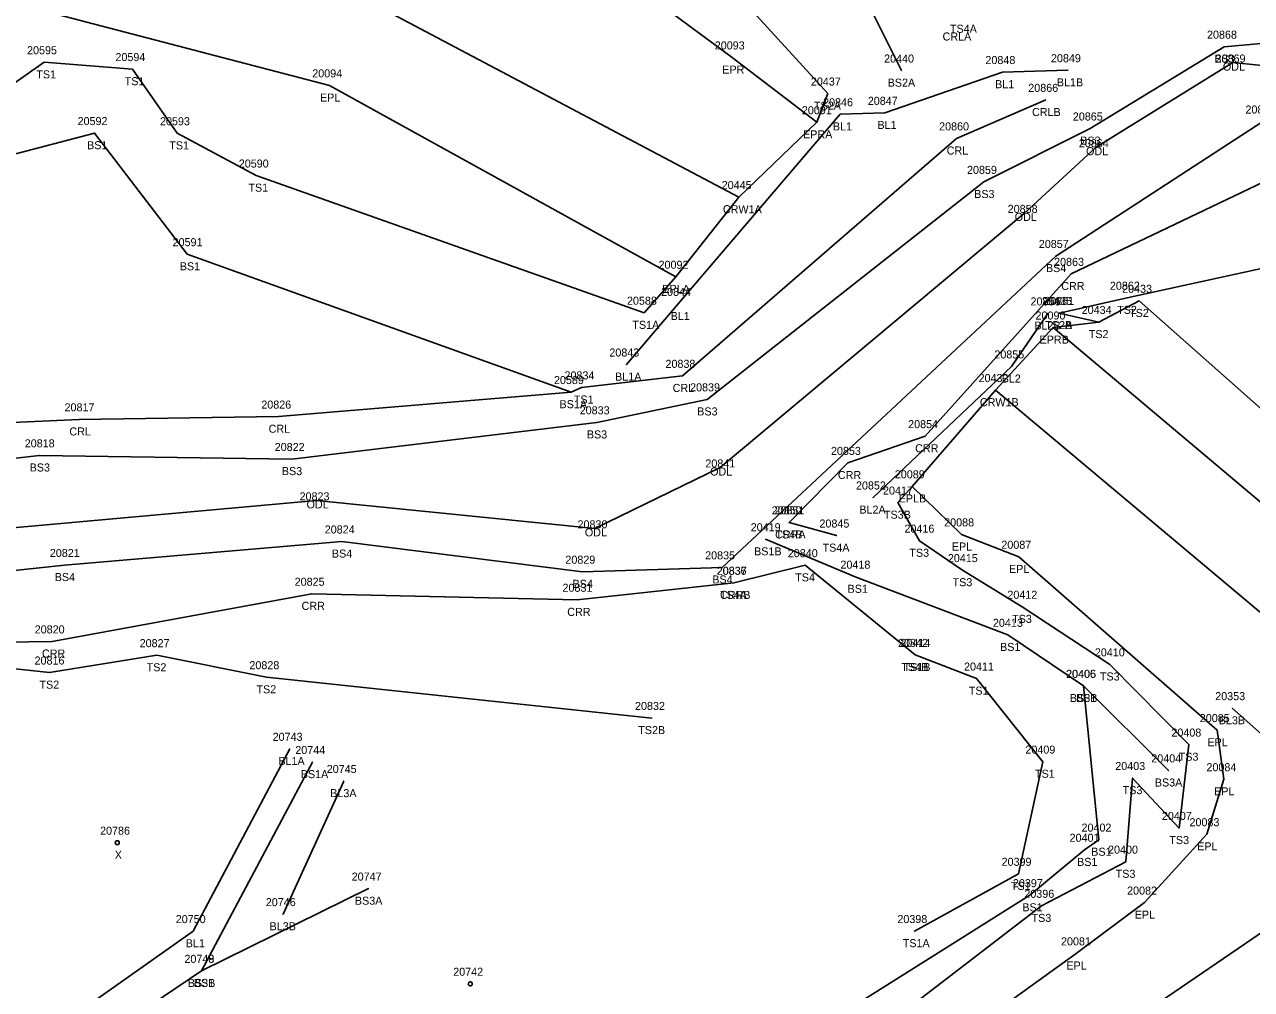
# Model space of a CAD drawing. Extents: x 1813127 to 1818290, y 1178171 to 1179900.
# Drawn here: x 1813651.9 to 1813804.5, y 1178619.3 to 1178739.3 of the extents above; entities that cross this region are included whole.
import ezdxf

# ---------------------------------------------------------------- set-up
doc = ezdxf.new("R2010")
doc.units = 0
for name, color, linetype in [('RD_DTM_BkLn1', 7, 'Continuous'), ('RD_DTM_BkLn2', 7, 'Continuous'), ('RD_EX_H2O', 7, 'Continuous'), ('RD_EX_H2O_txCode', 7, 'Continuous'), ('RD_EX_Road', 7, 'Continuous'), ('RD_EX_Road_txCode', 7, 'Continuous'), ('RD_SMD_Locator', 7, 'Continuous'), ('RD_SMD_Misc', 7, 'Continuous')]:
    doc.layers.add(name, color=color, linetype=linetype)

msp = doc.modelspace()

# ---------------------------------------------------------------- linework, layer by layer
at = {"layer": 'RD_DTM_BkLn1'}
for p, q in [((1813820.26, 1178638.1), (1813802.14, 1178654.3)), ((1813691.64, 1178645.24), (1813684.08, 1178628.68))]:
    msp.add_line(p, q, dxfattribs=at)
for points in [[(1813740.76, 1178717.86), (1813693.97, 1178742.65), (1813652.18, 1178753.85), (1813643.74, 1178755.64), (1813595, 1178763.51), (1813546.44, 1178770.61), (1813497.6, 1178777.62), (1813448.59, 1178785.89), (1813401.09, 1178795.04), (1813353.48, 1178806.76), (1813306.05, 1178819.85), (1813260.03, 1178834.12), (1813213.64, 1178849.47), (1813166.61, 1178866.29)], [(1813726.79, 1178697.04), (1813733.22, 1178704.58), (1813753.39, 1178728.16), (1813758.93, 1178728.34), (1813773.56, 1178733.41), (1813781.71, 1178733.64)], [(1813757.46, 1178680.5), (1813774.67, 1178696.8), (1813779.19, 1178703.39)], [(1814069.63, 1178419.56), (1814043.03, 1178443.95), (1814031.76, 1178453.98), (1813994.68, 1178489.07), (1813958.14, 1178523.5), (1813920.87, 1178558.86), (1813884.46, 1178593.47), (1813847.15, 1178628.98), (1813831.28, 1178643.33), (1813810.03, 1178662.5), (1813772.7, 1178693.86)], [(1813684.91, 1178649.24), (1813672.9, 1178626.57), (1813636.59, 1178600.97), (1813597.02, 1178573.71), (1813553.38, 1178551.14), (1813526.62, 1178527.89)], [(1813831.28, 1178643.33), (1813821.11, 1178637.41), (1813809.78, 1178629.12), (1813788.78, 1178614.79), (1813747.67, 1178586.85), (1813706.5, 1178558.14), (1813665.11, 1178528), (1813623.37, 1178496.83), (1813582.75, 1178466.66)]]:
    msp.add_lwpolyline(points, dxfattribs=at)
at = {"layer": 'RD_DTM_BkLn2'}
for p, q in [((1813752.92, 1178675.77), (1813747.03, 1178677.41)), ((1813794.23, 1178646.56), (1813783.65, 1178657.07)), ((1813694.73, 1178631.86), (1813673.94, 1178621.63))]:
    msp.add_line(p, q, dxfattribs=at)
for points in [[(1813751.85, 1178730.74), (1813741.17, 1178742.44), (1813717.67, 1178762.1), (1813698.84, 1178775.48), (1813689.15, 1178782.4), (1813688.55, 1178790.23), (1813686.56, 1178796.15), (1813687.57, 1178849.05), (1813684.25, 1178850.31), (1813686.08, 1178900.25), (1813688.49, 1178947.42), (1813691.04, 1178995.37), (1813694.64, 1179045.56)], [(1813761, 1178733.6), (1813755.04, 1178745.59), (1813738.22, 1178758.92), (1813720.3, 1178769.51), (1813690.62, 1178785.84)], [(1813728.98, 1178703.48), (1813680.74, 1178720.54), (1813670.9, 1178725.8), (1813665.35, 1178733.78), (1813654.36, 1178734.63), (1813647.32, 1178729.73), (1813639.1, 1178730.74), (1813591.11, 1178743.16), (1813543.28, 1178751.57), (1813511.7, 1178756.57), (1813494.92, 1178760.32), (1813445.74, 1178769.42), (1813422.91, 1178772.94), (1813422.78, 1178770.34)], [(1813501.61, 1178700.78), (1813535.62, 1178707.92), (1813578.65, 1178686.08), (1813588.2, 1178681.74), (1813622.61, 1178682.2), (1813653.79, 1178685.74), (1813685.17, 1178685.29), (1813723.1, 1178689.85), (1813736.83, 1178692.71), (1813771.26, 1178719.75), (1813784.46, 1178726.39), (1813801.14, 1178736.57), (1813819.08, 1178738.18), (1813840.25, 1178734.78), (1813848.44, 1178735.38), (1813862.15, 1178734.12), (1813885.61, 1178732.56), (1813903.34, 1178733.15)], [(1813719.9, 1178693.61), (1813672.18, 1178710.76), (1813660.65, 1178725.82), (1813637.51, 1178719.78), (1813596.2, 1178711.55), (1813573.69, 1178718.5), (1813539.15, 1178731.18), (1813521.54, 1178735.83), (1813479.61, 1178734.97)], [(1813751.85, 1178730.74), (1813750.48, 1178727.17), (1813740.76, 1178717.86)], [(1813494.55, 1178680.43), (1813533.86, 1178695.27), (1813573.03, 1178675.94), (1813630.33, 1178669.28), (1813656.92, 1178672.11), (1813691.39, 1178675.03), (1813721.31, 1178671.27), (1813738.7, 1178671.81), (1813780.2, 1178710.54), (1813805.93, 1178727.26), (1813819.91, 1178727.35), (1813841.4, 1178723.71), (1813860.66, 1178719.9), (1813869.89, 1178724.9), (1813872.35, 1178725.71), (1813884.47, 1178724.42), (1813903.61, 1178724.04)], [(1813740.76, 1178717.86), (1813732.94, 1178707.95), (1813728.98, 1178703.48)], [(1813780.61, 1178703.45), (1813789.06, 1178705.34), (1813820, 1178712.11), (1813829.02, 1178714.89)], [(1814080.77, 1178431.89), (1814053.55, 1178456.53), (1814053.55, 1178456.53), (1814043.11, 1178466.04), (1814008.23, 1178502.68), (1813981.17, 1178545.08), (1813940.17, 1178583.78), (1813898.27, 1178611.44), (1813860.48, 1178642.94), (1813824.26, 1178675.11), (1813790.56, 1178704.96), (1813785.53, 1178702.33), (1813780.61, 1178703.45)], [(1813785.53, 1178702.33), (1813779.87, 1178701.64), (1813772.7, 1178693.86), (1813762.33, 1178681.89), (1813760.53, 1178679.87)], [(1813648.32, 1178539.4), (1813697.26, 1178570.92), (1813738.71, 1178599.2), (1813778.43, 1178629.72), (1813788.89, 1178635.21), (1813789.75, 1178645.61), (1813795.55, 1178639.4), (1813796.73, 1178649.77), (1813786.93, 1178659.75), (1813776.01, 1178666.91), (1813768.6, 1178671.47), (1813763.23, 1178675.13), (1813760.53, 1178679.87)], [(1813647.13, 1178541.2), (1813695.54, 1178572.96), (1813738.1, 1178600.74), (1813742.95, 1178609.65), (1813776.97, 1178631.04), (1813783.78, 1178636.69), (1813785.55, 1178637.95), (1813783.65, 1178657.07), (1813774.21, 1178663.42), (1813755.25, 1178670.65), (1813744.09, 1178675.31)], [(1813740.16, 1178669.89), (1813749.02, 1178672.08), (1813762.69, 1178660.92)], [(1813623.26, 1178662.12), (1813655.04, 1178658.73), (1813668.37, 1178660.89), (1813682.02, 1178658.15), (1813729.97, 1178653.08)], [(1813762.61, 1178626.58), (1813775.57, 1178633.7), (1813778.57, 1178647.65), (1813770.33, 1178657.98), (1813762.69, 1178660.92)], [(1813687.73, 1178647.6), (1813673.94, 1178621.63), (1813639.04, 1178598.07), (1813598.95, 1178570.83), (1813556.33, 1178547.73), (1813528.18, 1178524.13)]]:
    msp.add_lwpolyline(points, dxfattribs=at)
at = {"layer": 'RD_EX_H2O'}
for points in [[(1813497.15, 1178691.5), (1813535.61, 1178703.5), (1813575.96, 1178680.52), (1813619.86, 1178677.62), (1813650.02, 1178676.71), (1813688.26, 1178680.15), (1813722.87, 1178676.67), (1813738.45, 1178684.24), (1813776.33, 1178715.9), (1813785.2, 1178724.07), (1813802.21, 1178734.6), (1813820.03, 1178732.78), (1813837.63, 1178729.78), (1813857.38, 1178730.32)], [(1813721.21, 1178694.19), (1813733.77, 1178695.63), (1813767.86, 1178725.16), (1813778.94, 1178729.95)], [(1813747.03, 1178677.41), (1813754.34, 1178684.8), (1813763.95, 1178688.13), (1813782.12, 1178708.31), (1813807.89, 1178720.63), (1813829.02, 1178714.89), (1813841.06, 1178713.13), (1813882.92, 1178708.73), (1813906.37, 1178716.29)], [(1813499.62, 1178706.37), (1813533.11, 1178716.31), (1813566.87, 1178706.45), (1813581.02, 1178703.79), (1813602.73, 1178697.66), (1813630.18, 1178688.94), (1813658.74, 1178690.22), (1813683.52, 1178690.56), (1813719.9, 1178693.61)], [(1813719.9, 1178693.61), (1813721.21, 1178694.19)], [(1813494.93, 1178677.14), (1813538.08, 1178685.02), (1813548.67, 1178684.4), (1813554.06, 1178674.83), (1813572.78, 1178667.8), (1813599.8, 1178663.18), (1813623.26, 1178662.12), (1813655.35, 1178662.6), (1813687.65, 1178668.53), (1813720.68, 1178667.78), (1813740.16, 1178669.89)]]:
    msp.add_lwpolyline(points, dxfattribs=at)
at = {"layer": 'RD_EX_Road'}
for points in [[(1813750.48, 1178727.17), (1813739.94, 1178735.23), (1813706.04, 1178760.25), (1813693.68, 1178773.78), (1813687.15, 1178785.68), (1813683.91, 1178796.53), (1813681.81, 1178824.01), (1813682.76, 1178849.48), (1813684.82, 1178900.28), (1813687.23, 1178946.66), (1813689.58, 1178995.92), (1813691.79, 1179045.45)], [(1813732.94, 1178707.95), (1813689.88, 1178731.75), (1813641.71, 1178744.36), (1813593.37, 1178752.09), (1813544.49, 1178758.77), (1813495.45, 1178766.29), (1813446.8, 1178774.66), (1813426.54, 1178777.95), (1813403.21, 1178782.55), (1813398.65, 1178783.84), (1813350.68, 1178796.09), (1813343.23, 1178797.92), (1813318.7, 1178804.23), (1813303.26, 1178808.85), (1813256.8, 1178823.17), (1813209.81, 1178838.91), (1813163.27, 1178855.57)], [(1814076.45, 1178427.4), (1814038.86, 1178461.87), (1814001.83, 1178496.62), (1813965.15, 1178531.54), (1813928.08, 1178567.1), (1813892.01, 1178601.23), (1813854.54, 1178636.51), (1813817.44, 1178670.03), (1813779.87, 1178701.64)], [(1813577.25, 1178474.27), (1813618.17, 1178504.26), (1813659.38, 1178535.26), (1813701.1, 1178565.69), (1813742.11, 1178594.54), (1813782.72, 1178623.8), (1813791.22, 1178630.12), (1813798.98, 1178638.62), (1813801.09, 1178645.46), (1813800.26, 1178651.57), (1813775.58, 1178673.13), (1813768.46, 1178675.91), (1813762.33, 1178681.89)]]:
    msp.add_lwpolyline(points, dxfattribs=at)
at = {"layer": 'RD_SMD_Locator'}
for centre, radius in [((1813801.14, 1178736.57), 0.001), ((1813654.36, 1178734.63), 0.001), ((1813739.94, 1178735.23), 0.001), ((1813802.21, 1178734.6), 0.001), ((1813665.35, 1178733.78), 0.001), ((1813761, 1178733.6), 0.001), ((1813773.56, 1178733.41), 0.001), ((1813781.71, 1178733.64), 0.001), ((1813689.88, 1178731.75), 0.001), ((1813751.85, 1178730.74), 0.001), ((1813778.94, 1178729.95), 0.001), ((1813758.93, 1178728.34), 0.001), ((1813750.48, 1178727.17), 0.001), ((1813753.39, 1178728.16), 0.001), ((1813660.65, 1178725.82), 0.001), ((1813670.9, 1178725.8), 0.001), ((1813784.46, 1178726.39), 0.001), ((1813767.86, 1178725.16), 0.001), ((1813785.2, 1178724.07), 0.001), ((1813680.74, 1178720.54), 0.001), ((1813771.26, 1178719.75), 0.001), ((1813740.76, 1178717.86), 0.001), ((1813776.33, 1178715.9), 0.001), ((1813672.18, 1178710.76), 0.001), ((1813780.2, 1178710.54), 0.001), ((1813732.94, 1178707.95), 0.001), ((1813782.12, 1178708.31), 0.001), ((1813733.22, 1178704.58), 0.001), ((1813789.06, 1178705.34), 0.001), ((1813790.56, 1178704.96), 0.001), ((1813728.98, 1178703.48), 0.001), ((1813779.19, 1178703.39), 0.001), ((1813780.61, 1178703.45), 0.001), ((1813780.61, 1178703.45), 0.001), ((1813785.53, 1178702.33), 0.001), ((1813779.87, 1178701.64), 0.001), ((1813726.79, 1178697.04), 0.001), ((1813774.67, 1178696.8), 0.001), ((1813733.77, 1178695.63), 0.001), ((1813719.9, 1178693.61), 0.001), ((1813721.21, 1178694.19), 0.001), ((1813772.7, 1178693.86), 0.001), ((1813736.83, 1178692.71), 0.001), ((1813658.74, 1178690.22), 0.001), ((1813683.52, 1178690.56), 0.001), ((1813723.1, 1178689.85), 0.001), ((1813763.95, 1178688.13), 0.001), ((1813653.79, 1178685.74), 0.001), ((1813685.17, 1178685.29), 0.001), ((1813738.45, 1178684.24), 0.001), ((1813754.34, 1178684.8), 0.001), ((1813762.33, 1178681.89), 0.001), ((1813688.26, 1178680.15), 0.001), ((1813757.46, 1178680.5), 0.001), ((1813760.53, 1178679.87), 0.001), ((1813722.87, 1178676.67), 0.001), ((1813747.03, 1178677.41), 0.001), ((1813747.03, 1178677.41), 0.001), ((1813691.39, 1178675.03), 0.001), ((1813744.09, 1178675.31), 0.001), ((1813752.92, 1178675.77), 0.001), ((1813763.23, 1178675.13), 0.001), ((1813768.46, 1178675.91), 0.001), ((1813656.92, 1178672.11), 0.001), ((1813738.7, 1178671.81), 0.001), ((1813749.02, 1178672.08), 0.001), ((1813775.58, 1178673.13), 0.001), ((1813721.31, 1178671.27), 0.001), ((1813755.25, 1178670.65), 0.001), ((1813768.6, 1178671.47), 0.001), ((1813740.16, 1178669.89), 0.001), ((1813740.16, 1178669.89), 0.001), ((1813687.65, 1178668.53), 0.001), ((1813720.68, 1178667.78), 0.001), ((1813776.01, 1178666.91), 0.001), ((1813774.21, 1178663.42), 0.001), ((1813655.35, 1178662.6), 0.001), ((1813668.37, 1178660.89), 0.001), ((1813762.69, 1178660.92), 0.001), ((1813762.69, 1178660.92), 0.001), ((1813786.93, 1178659.75), 0.001), ((1813655.04, 1178658.73), 0.001), ((1813682.02, 1178658.15), 0.001), ((1813770.33, 1178657.98), 0.001), ((1813783.65, 1178657.07), 0.001), ((1813783.65, 1178657.07), 0.001), ((1813802.14, 1178654.3), 0.001), ((1813729.97, 1178653.08), 0.001), ((1813800.26, 1178651.57), 0.001), ((1813684.91, 1178649.24), 0.001), ((1813796.73, 1178649.77), 0.001), ((1813687.73, 1178647.6), 0.001), ((1813778.57, 1178647.65), 0.001), ((1813794.23, 1178646.56), 0.001), ((1813691.64, 1178645.24), 0.001), ((1813789.75, 1178645.61), 0.001), ((1813801.09, 1178645.46), 0.001), ((1813795.55, 1178639.4), 0.001), ((1813798.98, 1178638.62), 0.001), ((1813663.47, 1178637.57), 0.25), ((1813785.55, 1178637.95), 0.001), ((1813783.78, 1178636.69), 0.001), ((1813788.89, 1178635.21), 0.001), ((1813775.57, 1178633.7), 0.001), ((1813694.73, 1178631.86), 0.001), ((1813776.97, 1178631.04), 0.001), ((1813778.43, 1178629.72), 0.001), ((1813791.22, 1178630.12), 0.001), ((1813684.08, 1178628.68), 0.001), ((1813672.9, 1178626.57), 0.001), ((1813762.61, 1178626.58), 0.001), ((1813782.72, 1178623.8), 0.001), ((1813673.94, 1178621.63), 0.001), ((1813673.94, 1178621.63), 0.001), ((1813707.37, 1178620.02), 0.25)]:
    msp.add_circle(centre, radius, dxfattribs=at)

# ---------------------------------------------------------------- texts
at = {"layer": 'RD_EX_H2O_txCode'}
for s, p in [('CRLA', (1813766.11, 1178737.34)), ('20869', (1813800.07, 1178734.6)), ('ODL', (1813800.97, 1178733.6)), ('20866', (1813776.77, 1178730.95)), ('CRLB', (1813777.24, 1178727.95)), ('20860', (1813765.68, 1178726.16)), ('CRL', (1813766.63, 1178723.16)), ('20864', (1813783.06, 1178724.07)), ('ODL', (1813783.96, 1178723.07)), ('20858', (1813774.21, 1178715.9)), ('ODL', (1813775.08, 1178714.9)), ('20863', (1813779.98, 1178709.31)), ('CRR', (1813780.87, 1178706.31)), ('20838', (1813731.65, 1178696.63)), ('CRL', (1813732.54, 1178693.63)), ('20817', (1813656.91, 1178691.22)), ('20826', (1813681.38, 1178691.56)), ('20854', (1813761.83, 1178689.13)), ('CRL', (1813657.51, 1178688.22)), ('CRL', (1813682.29, 1178688.56)), ('CRR', (1813762.7, 1178686.13)), ('20853', (1813752.23, 1178685.8)), ('20841', (1813736.61, 1178684.24)), ('ODL', (1813737.2, 1178683.24)), ('CRR', (1813753.09, 1178682.8)), ('20823', (1813686.14, 1178680.15)), ('ODL', (1813687.01, 1178679.15)), ('20851', (1813745.2, 1178678.41)), ('20830', (1813720.71, 1178676.67)), ('ODL', (1813721.62, 1178675.67)), ('CRRA', (1813745.29, 1178675.41)), ('20836', (1813738.01, 1178670.89)), ('20825', (1813685.53, 1178669.53)), ('20831', (1813718.84, 1178668.78)), ('CRRB', (1813738.43, 1178667.89)), ('CRR', (1813686.39, 1178666.53)), ('CRR', (1813719.43, 1178665.78)), ('20820', (1813653.2, 1178663.6)), ('CRR', (1813654.1, 1178660.6))]:
    msp.add_text(s, height=1, dxfattribs=at).set_placement(p)
at = {"layer": 'RD_EX_Road_txCode'}
for s, p in [('20093', (1813737.78, 1178736.23)), ('20094', (1813687.72, 1178732.75)), ('EPR', (1813738.71, 1178733.23)), ('EPL', (1813688.68, 1178729.75)), ('20091', (1813748.61, 1178728.17)), ('EPRA', (1813748.76, 1178725.17)), ('20092', (1813730.79, 1178708.95)), ('EPLA', (1813731.25, 1178705.95)), ('20090', (1813777.67, 1178702.64)), ('EPRB', (1813778.17, 1178699.64)), ('20089', (1813760.17, 1178682.89)), ('EPLB', (1813760.65, 1178679.89)), ('20088', (1813766.31, 1178676.91)), ('EPL', (1813767.26, 1178673.91)), ('20087', (1813773.42, 1178674.13)), ('EPL', (1813774.37, 1178671.13)), ('20085', (1813798.1, 1178652.57)), ('EPL', (1813799.05, 1178649.57)), ('20084', (1813798.93, 1178646.46)), ('EPL', (1813799.88, 1178643.46)), ('20083', (1813796.82, 1178639.62)), ('EPL', (1813797.77, 1178636.62)), ('20082', (1813789.06, 1178631.12)), ('EPL', (1813790.01, 1178628.12)), ('20081', (1813780.84, 1178624.8)), ('EPL', (1813781.51, 1178621.8))]:
    msp.add_text(s, height=1, dxfattribs=at).set_placement(p)
at = {"layer": 'RD_SMD_Misc'}
for s, p in [('TS4A', (1813767.03, 1178738.3)), ('20868', (1813799, 1178737.57)), ('20595', (1813652.25, 1178735.63)), ('20594', (1813663.24, 1178734.78)), ('20440', (1813758.84, 1178734.6)), ('20848', (1813771.44, 1178734.41)), ('20849', (1813779.59, 1178734.64)), ('BS3', (1813799.91, 1178734.57)), ('TS1', (1813653.4, 1178732.63)), ('TS1', (1813664.39, 1178731.78)), ('20437', (1813749.73, 1178731.74)), ('BS2A', (1813759.28, 1178731.6)), ('BL1', (1813772.64, 1178731.41)), ('BL1B', (1813780.32, 1178731.64)), ('20846', (1813751.25, 1178729.16)), ('20847', (1813756.81, 1178729.34)), ('TS2A', (1813750.12, 1178728.74)), ('20865', (1813782.31, 1178727.39)), ('20870', (1813803.78, 1178728.26)), ('20592', (1813658.53, 1178726.82)), ('20593', (1813668.78, 1178726.8)), ('BL1', (1813752.47, 1178726.16)), ('BL1', (1813758.01, 1178726.34)), ('BS3', (1813783.23, 1178724.39)), ('BS1', (1813659.71, 1178723.82)), ('TS1', (1813669.94, 1178723.8)), ('20590', (1813678.58, 1178721.54)), ('20859', (1813769.15, 1178720.75)), ('TS1', (1813679.78, 1178718.54)), ('20445', (1813738.64, 1178718.86)), ('BS3', (1813770.04, 1178717.75)), ('CRW1A', (1813738.79, 1178715.86)), ('20591', (1813670.35, 1178711.76)), ('20857', (1813778.08, 1178711.54)), ('BS1', (1813671.24, 1178708.76)), ('BS4', (1813778.97, 1178708.54)), ('20862', (1813786.92, 1178706.34)), ('20433', (1813788.44, 1178705.96)), ('20588', (1813726.86, 1178704.48)), ('20844', (1813731.1, 1178705.58)), ('20856', (1813777.05, 1178704.39)), ('20435', (1813778.49, 1178704.45)), ('20861', (1813778.75, 1178704.45)), ('20434', (1813783.41, 1178703.33)), ('TS2', (1813787.82, 1178703.34)), ('TS2', (1813789.31, 1178702.96)), ('TS1A', (1813727.53, 1178701.48)), ('BL1', (1813732.29, 1178702.58)), ('BL2B', (1813777.52, 1178701.39)), ('TS2A', (1813778.88, 1178701.45)), ('TS2B', (1813778.89, 1178701.45)), ('TS2', (1813784.29, 1178700.33)), ('20843', (1813724.67, 1178698.04)), ('20855', (1813772.55, 1178697.8)), ('20834', (1813719.09, 1178695.19)), ('20589', (1813717.78, 1178694.61)), ('BL1A', (1813725.38, 1178695.04)), ('20839', (1813734.71, 1178693.71)), ('20432', (1813770.59, 1178694.86)), ('BL2', (1813773.46, 1178694.8)), ('TS1', (1813720.25, 1178692.19)), ('BS1A', (1813718.47, 1178691.61)), ('20833', (1813720.98, 1178690.85)), ('BS3', (1813735.6, 1178690.71)), ('CRW1B', (1813770.75, 1178691.86)), ('BS3', (1813721.87, 1178687.85)), ('20818', (1813651.96, 1178686.74)), ('20822', (1813683.05, 1178686.29)), ('BS3', (1813652.57, 1178683.74)), ('BS3', (1813683.94, 1178683.29)), ('20852', (1813755.34, 1178681.5)), ('20417', (1813758.7, 1178680.87)), ('20850', (1813744.87, 1178678.41)), ('BL2A', (1813755.76, 1178678.5)), ('TS3B', (1813758.82, 1178677.87)), ('20824', (1813689.27, 1178676.03)), ('20419', (1813742.25, 1178676.31)), ('TS4B', (1813745.32, 1178675.41)), ('20845', (1813750.8, 1178676.77)), ('20416', (1813761.37, 1178676.13)), ('20821', (1813655.08, 1178673.11)), ('BS4', (1813690.16, 1178673.03)), ('20835', (1813736.58, 1178672.81)), ('BS1B', (1813742.67, 1178673.31)), ('20840', (1813746.86, 1178673.08)), ('TS4A', (1813751.19, 1178673.77)), ('TS3', (1813761.98, 1178673.13)), ('20415', (1813766.77, 1178672.47)), ('20829', (1813719.2, 1178672.27)), ('20837', (1813738.04, 1178670.89)), ('20418', (1813753.41, 1178671.65)), ('BS4', (1813655.69, 1178670.11)), ('BS4', (1813720.09, 1178669.27)), ('BS4', (1813737.47, 1178669.81)), ('TS4', (1813747.78, 1178670.08)), ('TS3', (1813767.36, 1178669.47)), ('TS4A', (1813738.42, 1178667.89)), ('BS1', (1813754.3, 1178668.65)), ('20412', (1813774.17, 1178667.91)), ('TS3', (1813774.76, 1178664.91)), ('20413', (1813772.37, 1178664.42)), ('20827', (1813666.25, 1178661.89)), ('20842', (1813760.57, 1178661.92)), ('20414', (1813760.86, 1178661.92)), ('BS1', (1813773.26, 1178661.42)), ('20410', (1813785.05, 1178660.75)), ('20816', (1813653.18, 1178659.73)), ('TS2', (1813667.12, 1178658.89)), ('20828', (1813679.9, 1178659.15)), ('TS4B', (1813760.98, 1178658.92)), ('TS1B', (1813761.26, 1178658.92)), ('20411', (1813768.78, 1178658.98)), ('20406', (1813781.46, 1178658.07)), ('20405', (1813781.49, 1178658.07)), ('TS3', (1813785.68, 1178657.75)), ('TS2', (1813653.79, 1178656.73)), ('TS2', (1813680.78, 1178656.15)), ('TS1', (1813769.37, 1178655.98)), ('20832', (1813727.86, 1178654.08)), ('BS3B', (1813781.95, 1178655.07)), ('BS1', (1813782.7, 1178655.07)), ('20353', (1813800.02, 1178655.3)), ('TS2B', (1813728.26, 1178651.08)), ('BL3B', (1813800.46, 1178652.3)), ('20743', (1813682.79, 1178650.24)), ('20408', (1813794.57, 1178650.77)), ('20744', (1813685.61, 1178648.6)), ('20409', (1813776.41, 1178648.65)), ('BL1A', (1813683.5, 1178647.24)), ('20403', (1813787.59, 1178646.61)), ('20404', (1813792.07, 1178647.56)), ('TS3', (1813795.48, 1178647.77)), ('BS1A', (1813686.29, 1178645.6)), ('20745', (1813689.52, 1178646.24)), ('TS1', (1813777.61, 1178645.65)), ('TS3', (1813788.51, 1178643.61)), ('BS3A', (1813792.51, 1178644.56)), ('BL3A', (1813689.95, 1178643.24)), ('20407', (1813793.39, 1178640.4)), ('20402', (1813783.39, 1178638.95)), ('20786', (1813661.33, 1178638.57)), ('20401', (1813781.91, 1178637.69)), ('TS3', (1813794.31, 1178637.4)), ('BS1', (1813784.6, 1178635.95)), ('20400', (1813786.69, 1178636.21)), ('X', (1813663.16, 1178635.57)), ('20399', (1813773.45, 1178634.7)), ('BS1', (1813782.84, 1178634.69)), ('20747', (1813692.62, 1178632.86)), ('TS3', (1813787.64, 1178633.21)), ('TS1', (1813774.61, 1178631.7)), ('20397', (1813774.86, 1178632.04)), ('20746', (1813681.94, 1178629.68)), ('BS3A', (1813693.02, 1178629.86)), ('20396', (1813776.28, 1178630.72)), ('BS1', (1813776.03, 1178629.04)), ('20750', (1813670.74, 1178627.57)), ('BL3B', (1813682.41, 1178626.68)), ('20398', (1813760.49, 1178627.58)), ('TS3', (1813777.18, 1178627.72)), ('BL1', (1813671.98, 1178624.57)), ('TS1A', (1813761.16, 1178624.58)), ('20748', (1813671.82, 1178622.63)), ('20749', (1813671.82, 1178622.63)), ('20742', (1813705.25, 1178621.02)), ('BS3B', (1813672.24, 1178619.63)), ('BS1', (1813672.99, 1178619.63))]:
    msp.add_text(s, height=1, dxfattribs=at).set_placement(p)

doc.saveas('drawing.dxf')
